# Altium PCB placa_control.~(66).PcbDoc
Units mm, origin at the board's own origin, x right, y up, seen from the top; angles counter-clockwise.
Board outline 71.3 x 86.83 mm, 2 copper layers (Top Layer, Bottom Layer); 36 components, 32 nets, 145 pads, 101 vias.
Unrouted connection lines stored in the file: 1.
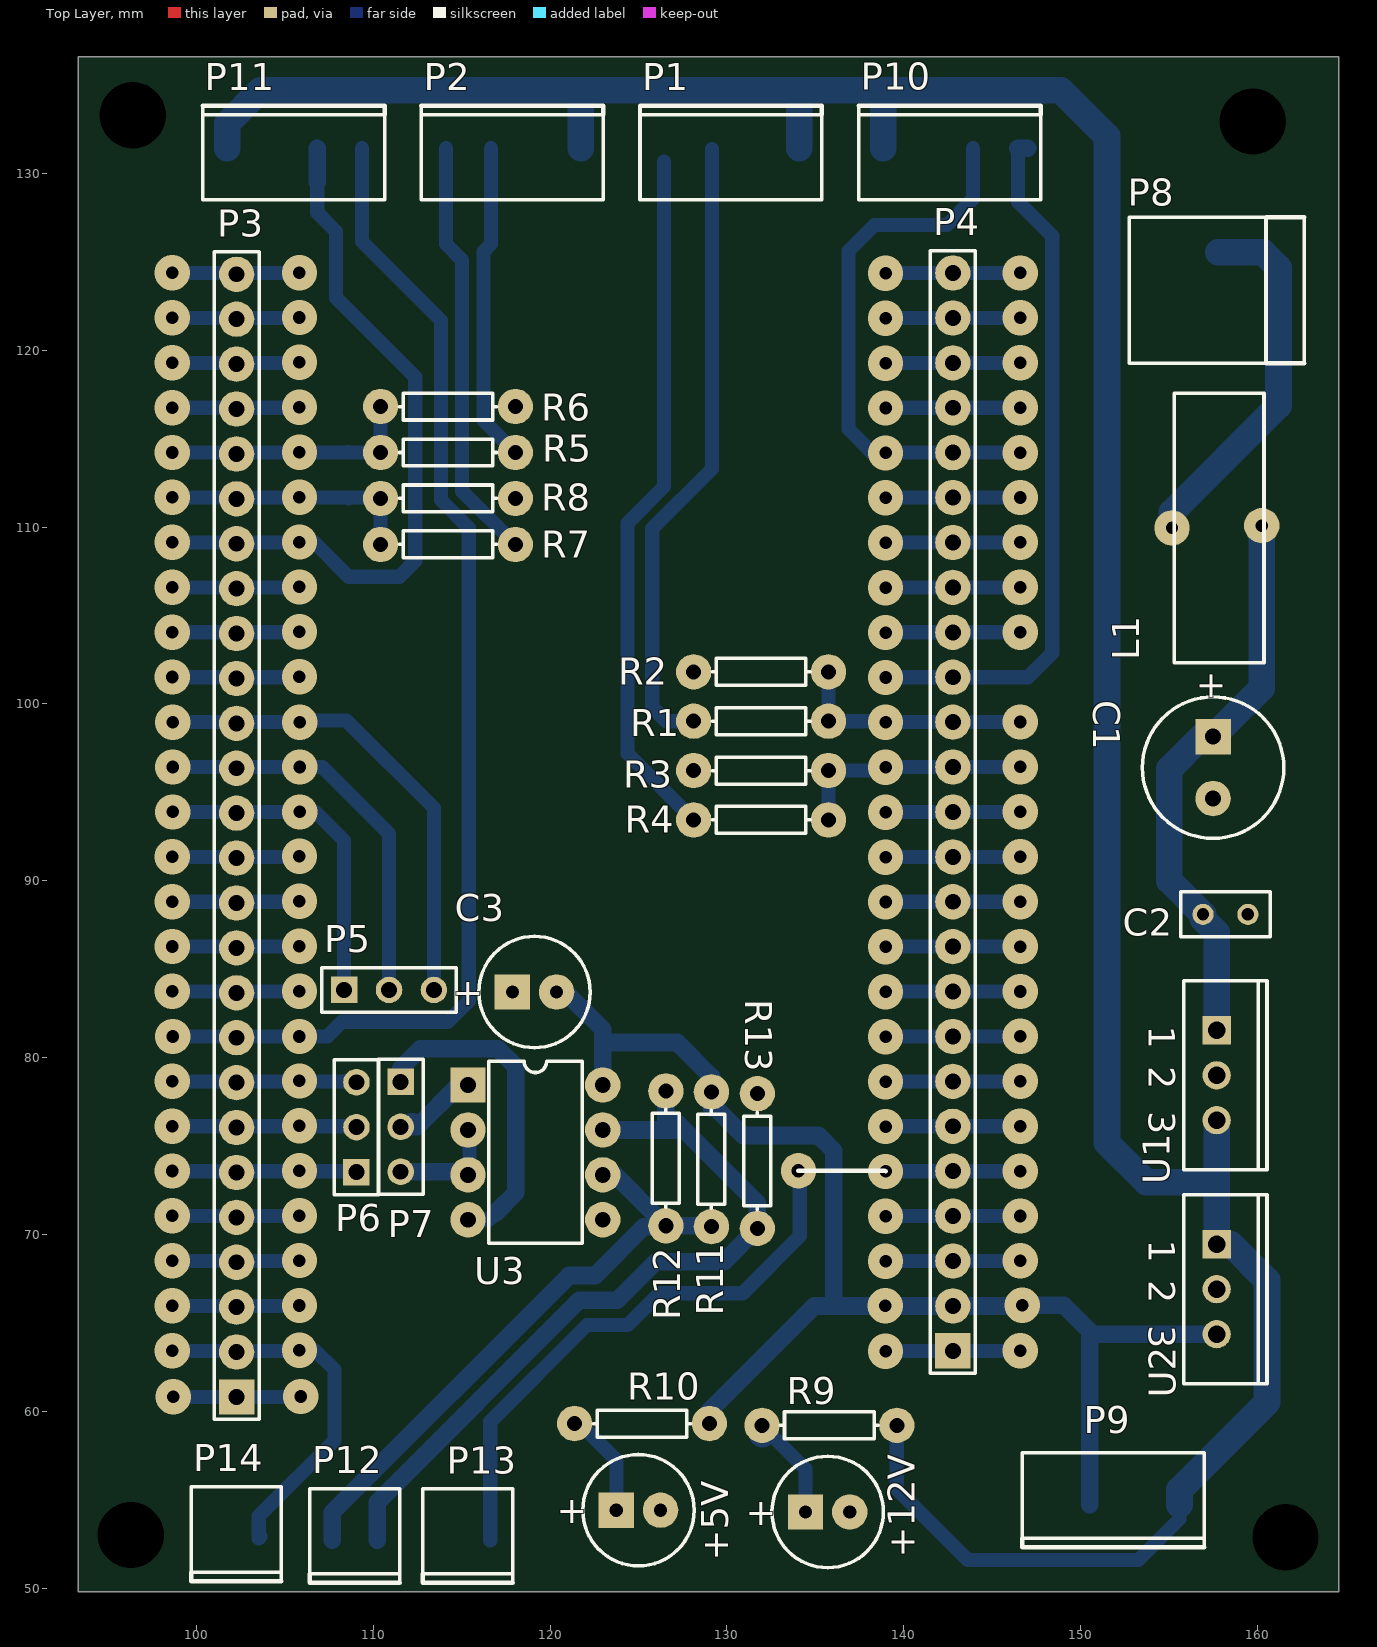
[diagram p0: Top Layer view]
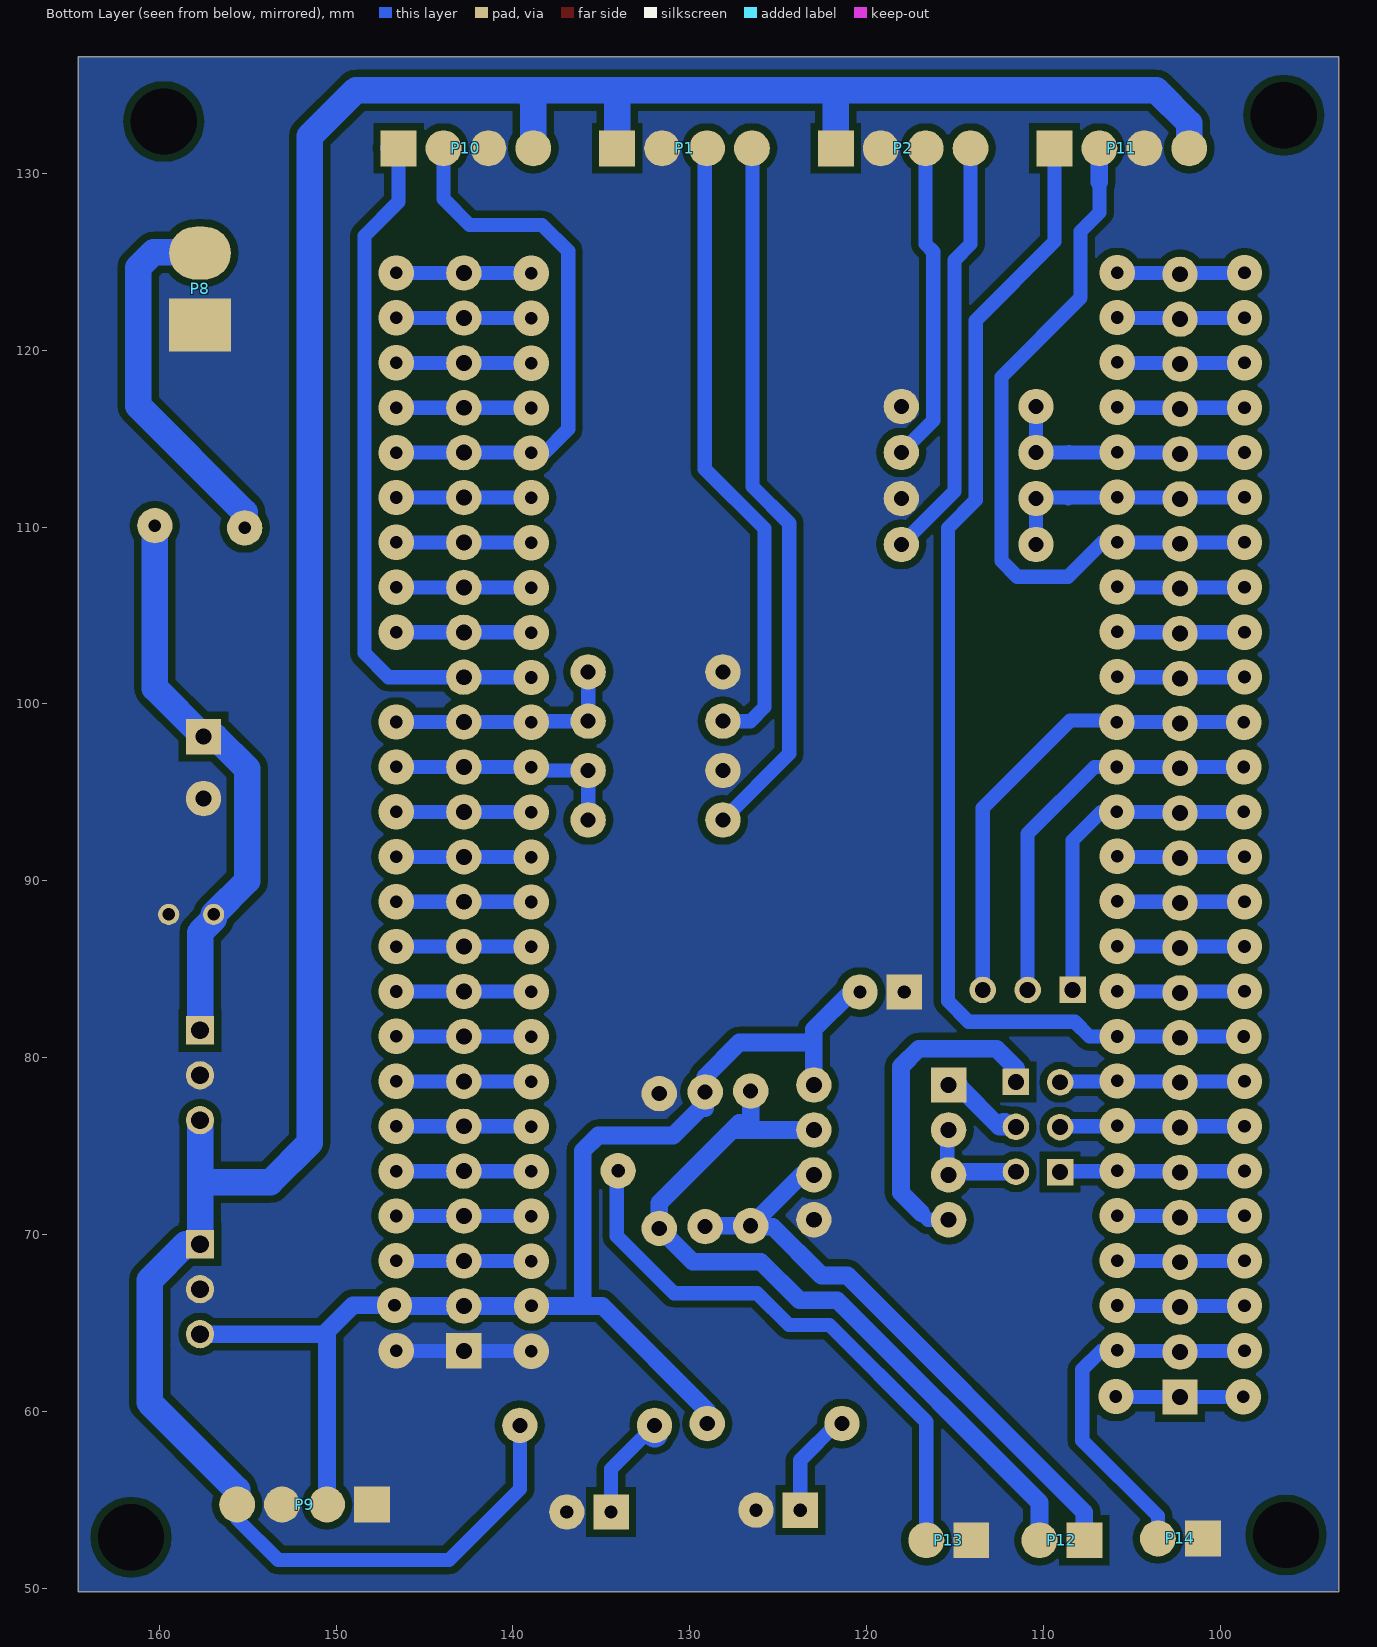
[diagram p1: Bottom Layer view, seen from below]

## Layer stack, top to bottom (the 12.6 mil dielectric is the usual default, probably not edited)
Top Layer: signal copper 0.0356
Dielectric: dielectric 0.32, FR-4, Dk 4.8
Bottom Layer: signal copper 0.0356

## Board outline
93.3,136.6 164.6,136.6 164.6,49.775 93.3,49.775

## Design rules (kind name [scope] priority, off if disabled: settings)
Clearance [All] p1: gap=0.4
ComponentClearance [All] p1: gap=0.254 collisioncheckmode=2 verticalgap=0.254
PlaneConnect [All] p1: planeconnectstyle=Direct reliefexpansion=0.508 reliefentries=4 reliefconductorwidth=0.6 reliefairgap=0.254
PolygonConnect [All] p1: connectstyle=Direct reliefconductorwidth=0.6 reliefentries=4 polygonreliefangle="90 Angle"
RoomDefinition REGULADOR [InComponentClass('REGULADOR')] p1: confinementstyle=ConfineIn formatcopy=TRUE lockcomponents=FALSE outline 119.85,49.75 164.625,49.75 164.625,133.175 119.85,133.175
RoomDefinition INTERFAZ [InComponentClass('INTERFAZ')] p2: confinementstyle=ConfineIn formatcopy=TRUE lockcomponents=FALSE outline 106.825,64.6 139.725,64.6 139.725,90 106.825,90
RoomDefinition ENCODER [InComponentClass('ENCODER')] p3: confinementstyle=ConfineIn formatcopy=TRUE lockcomponents=FALSE outline 149.05,93.65 149.05,135.875 98.875,135.875 98.875,93.65
RoomDefinition BOARD-ARM [InComponentClass('BOARD-ARM')] p4: confinementstyle=ConfineIn formatcopy=TRUE lockcomponents=FALSE outline 147.988,49.325 95.35,49.325 95.35,129.85 147.988,129.85
RoomDefinition placa_control_esquema [InComponentClass('placa_control_esquema')] p5: confinementstyle=ConfineIn formatcopy=TRUE lockcomponents=FALSE outline 93.3,49.75 164.6,49.75 164.6,136.6 93.3,136.6
RoutingVias [All] p1: holewidth=0.711 width=2 viastyle="Through Hole" minholewidth=0.711 minwidth=1.27 maxholewidth=0.711 maxwidth=2
SolderMaskExpansion [All] p1: expansion=0.102
TestPointUsage [All] p1: valid=0 allowmultiple=FALSE
Testpoint [All] p1: side=15 testpointundercomponent=TRUE minsize=1.016 maxsize=2.54 preferedsize=1.524 minholesize=0 maxholesize=1.016 preferedholesize=0.813 testpointgrid=0.025 style=1023 order=0123456789
Width [All] p1: maxlimit=1.5 minlimit=0.8 preferedwidth=0.8
17 further rules are at their usual default settings.

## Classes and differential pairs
component class placa_control_esquema: P9 P10 P11
component class REGULADOR: +5V +12V C1 C2 L1 P8 R9 R10 U1 U2
component class BOARD-ARM: P3 P4 P5 P6 P7 P13 P14
component class ENCODER: P1 P2 R1 R2 R3 R4 R5 R6 R7 R8
component class INTERFAZ: C3 P12 R11 R12 R13 U3

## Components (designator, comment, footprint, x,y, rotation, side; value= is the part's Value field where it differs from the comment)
+5V "LED2" CAPPR2.5-6.3X5 125,54.4 r0 top
+12V "LED2" CAPPR2.5-6.3X5 135.7,54.3 r0 top
C1 "Cap Pol3" CAPPR3.5-8X15 157.5,96.4 r270 top
C2 "Cap" RAD-0.1 158.2,88.1 r180 top
C3 "Cap" CAPPR2.5-6.3X5 119.119,83.708 r0 top
L1 "Inductor Iron" bobina_Choque 155.3,112.5 r270 top
P1 "Header 4" HDR1X5 126.483,139.05 r180 top
P2 "Header 4" HDR1X5 114.117,139.05 r180 top
P3 "header26" HDR1x26 107.35,93.825 r90 top
P4 "Header 25" HDR1X25 142.78,63.415 r90 top
P5 "Header 3" HDR1X3 108.35,83.825 r0 top
P6 "Header 3" HDR1X3 109.05,73.525 r90 top
P7 "Header 3" HDR1X3 111.55,78.625 r270 top
P8 "Header 2" pwheader1x2 157.7,123.6 r90 top
P9 "Header 4" HDR1X5 155.6,47.1 r0 top
P10 "Header 4" HDR1X5 138.85,139.05 r180 top
P11 "Header 4" HDR1X5 101.75,139.05 r180 top
P12 "Header 2" wf2s 115.3,52.7 r0 top
P13 "Header 2" wf2s 121.7,52.7 r0 top
P14 "Header 2" wf2s 108.6,52.8 r0 top
R1 "metal film 2%" AXIAL-0.3 131.934,99.027 r180 top
R2 "metal film 2%" AXIAL-0.3 131.934,101.819 r0 top
R3 "metal film 2%" AXIAL-0.3 131.934,93.443 r180 top
R4 "metal film 2%" AXIAL-0.3 131.934,96.235 r0 top
R5 "metal film 2%" AXIAL-0.3 114.225,114.225 r0 top
R6 "metal film 2%" AXIAL-0.3 114.225,116.825 r180 top
R7 "metal film 2%" AXIAL-0.3 114.225,109.025 r0 top
R8 "metal film 2%" AXIAL-0.3 114.225,111.625 r180 top
R9 "Carbon 1/8w 5%" AXIAL-0.3 135.8,59.2 r0 top
R10 "Carbon 1/8w 5%" AXIAL-0.3 125.2,59.3 r0 top
R11 "Carbon 1/8w 5%" AXIAL-0.3 129.125,74.25 r90 top
R12 "Carbon 1/8w 5%" AXIAL-0.3 126.551,74.3 r270 top
R13 "Carbon 1/8w 5%" AXIAL-0.3 131.725,74.15 r270 top
U1 "LM78L12ACZ" T03B 157.7,79 r270 top
U2 "LM78L05ACZ" T03B 157.7,66.9 r270 top
U3 "SN75176BP" 626-05 119.169,74.64 r270 top

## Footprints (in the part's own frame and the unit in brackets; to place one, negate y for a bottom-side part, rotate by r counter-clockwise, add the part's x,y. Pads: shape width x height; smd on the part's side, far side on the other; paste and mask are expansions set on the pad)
626-05 [mm] "DIP; 8 Leads; Row Spacing 7.62 mm; Pitch 2.54 mm"
  rect 2x2 hole 0.9: 1(-3.81,-3.81)
  round 2 hole 0.9: 2(-1.27,-3.81) 3(1.27,-3.81) 4(3.81,-3.81) 5(3.81,3.81) 6(1.27,3.81) 7(-1.27,3.81) 8(-3.81,3.81)
  silkscreen extent -5.15,-2.65 5.15,2.65
AXIAL-0.3 [mm] "Resistor; 2 Leads"
  round 2 hole 0.85: 1(-3.81,0) 2(3.81,0)
  silkscreen extent -2.77,-0.76 2.77,0.76
bobina_Choque [mm]
  round 2 hole 0.7: 1(2.54,-0.127) 2(2.413,4.953)
  silkscreen extent -5.08,0 10.16,5.08
CAPPR2.5-6.3X5 [mm] "Capacitor, Electrolytic, Radial; Body 6.3 x 5 mm (Dia.xH typ); Pin Spacing 2.5 mm (typ)"
  rect 2x2 hole 0.75: 1(-1.25,0)
  round 2 hole 0.75: 2(1.25,0)
  silkscreen extent -3.15,-3.15 3.15,3.15
CAPPR3.5-8X15 [mm] "Capacitor, Electrolytic, Radial; Body 8 x 15 mm (Dia.xH typ); Pin Spacing 3.5 mm (typ)"
  rect 2x2 hole 0.9: 1(-1.75,0)
  round 2 hole 0.9: 2(1.75,0)
  silkscreen extent -4,-4 4,4
HDR1X3 [mm] "Connector; Header; 3 Position"
  rect 1.5x1.5 hole 0.9: 1(0,0)
  round 1.5 hole 0.9: 2(2.54,0) 3(5.08,0)
  silkscreen extent -1.27,-1.27 6.35,1.27
HDR1X5 [mil]
  rect 80x80 smd far side: 1(-300,300)
  round 80 smd far side: 2(-200,300) 3(-100,300) 4(0,300)
  silkscreen extent -350,205 55,415
HDR1X25 [mm] "Connector; Header; 25 Position"
  rect 2x2 hole 0.9: 1(0,0)
  round 2 hole 0.9: 2(2.54,0) 3(5.08,0) 4(7.62,0) 5(10.16,0) 6(12.7,0) 7(15.24,0) 8(17.78,0) 9(20.32,0) 10(22.86,0) 11(25.4,0) 12(27.94,0) 13(30.48,0) 14(33.02,0) 15(35.56,0) 16(38.1,0) 17(40.64,0) 18(43.18,0) 19(45.72,0) 20(48.26,0) 21(50.8,0) 22(53.34,0) 23(55.88,0) 24(58.42,0) 25(60.96,0)
  silkscreen extent -1.27,-1.27 62.23,1.27
HDR1x26 [mm]
  rect 2x2 hole 0.9: 1(-33.02,5.08)
  round 2 hole 0.9: 2(-30.48,5.08) 3(-27.94,5.08) 4(-25.4,5.08) 5(-22.86,5.08) 6(-20.32,5.08) 7(-17.78,5.08) 8(-15.24,5.08) 9(-12.7,5.08) 10(-10.16,5.08) 11(-7.62,5.08) 12(-5.08,5.08) 13(-2.54,5.08) 14(0,5.08) 15(2.54,5.08) 16(5.08,5.08) 17(7.62,5.08) 18(10.16,5.08) 19(12.7,5.08) 20(15.24,5.08) 21(17.78,5.08) 22(20.32,5.08) 23(22.86,5.08) 24(25.4,5.08) 25(27.94,5.08) 26(30.48,5.08)
  silkscreen extent -34.29,3.81 31.75,6.35
pwheader1x2 [mm]
  rect 3x3.5 smd far side: 1(-2.159,0)
  oval 3x3.5 smd far side: 2(1.905,0)
  silkscreen extent -4.32,-4.95 3.94,4.95
RAD-0.1 [mm] "Indicating Instrument; 2 Leads"
  round 1.2 hole 0.7: 1(-1.27,0) 2(1.27,0)
  silkscreen extent -2.54,-1.27 2.54,1.27
T03B [mm] "TO, Thru-Hole, Vertical, Heatsink Mounted; 3 In-Line Leads; Pitch 2.54 mm"
  rect 1.6x1.6 hole 1: 1(-2.54,0)
  round 1.6 hole 1: 2(0,0) 3(2.54,0)
  silkscreen extent -5.35,-1.85 5.35,2.85
wf2s [mil]
  rect 80x80 smd far side: 1(-300,0)
  round 80 smd far side: 2(-200,0)
  silkscreen extent -350,-95 -150,115

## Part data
+5V +12V: "Typical RED, GREEN, YELLOW, AMBER GaAs LED"
C1: "Polarized Capacitor 35V"
C2 C3: "Capacitor"
L1: "Magnetic-Core Inductor"
P1 P2 P9 P10 P11: "Header, 4-Pin"
P3: library part Component_1
P4: "Header, 25-Pin"
P5 P6 P7: "Header, 3-Pin"
P8 P12 P13 P14: "Header, 2-Pin"
R1 R2 R3 R4 R5 R6 R7 R8 R9 R10 R11 R12 R13: library part "Res Semi", "Semiconductor Resistor"
U1 U2: "3-Terminal Positive Regulator"
U3: "Differential Bus Transceiver"

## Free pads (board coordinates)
  round 1.524 hole 3.75: 0(96.275,53) 0(96.4,133.3) 0(159.75,132.95) 0(161.6,52.875)
  round 2 hole 0.762: 0(134.05,73.6)

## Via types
v1: diameter 2, hole 0.711, Top Layer to Bottom Layer, 101 vias

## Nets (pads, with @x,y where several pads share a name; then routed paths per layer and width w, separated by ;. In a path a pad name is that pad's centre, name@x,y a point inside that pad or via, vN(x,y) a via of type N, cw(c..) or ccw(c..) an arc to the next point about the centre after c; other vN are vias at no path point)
+5V: C3.2 P4.2 P9.2 R10.2 R11.2 U2.3 U3.8 | length 71.6
  Bottom Layer w1: C3.2@120.867,83.708 122.979,81.596 U3.8 U3.8@123.2,78.45 ; 122.979,80.85 127.2,80.85 R11.2@129.125,78.925 ; R10.2 129.01,60.01 134.955,65.955 P4.2 142.785,65.95 v1@146.05,65.95 ; R11.2@129.125,77.15 129.125,77.4 130.932,75.593 135.182,75.593 136.05,74.725 136.05,66.05 ; v1(146.7,66) 149.05,66 150.69,64.36 U2.3 ; P9.2 150.52,64.18
  other v1: 138.95,65.955
+12V: P1.1 P2.1 P9.4 P10.4 P11.4 R9.2 U1.3 U2.1 | length 173.9
  Bottom Layer w0.8: R9.2 139.61,55.59 143.625,51.575 153.275,51.575 155.6,53.9 P9.4
  Bottom Layer w1.5: P11.4 101.75,132.85 103.625,134.725 148.875,134.725 151.5,132.1 151.5,75.175 153.725,72.95 157.7,72.95 ; P2.1 121.737,134.212 121.75,134.225 ; P1.1 134.103,134.178 134.15,134.225 ; P10.4 138.85,134.15 138.925,134.225 ; P9.4 155.6,55.55 160.55,60.5 160.55,63.725 ; U1.3 U2.1 158.51,69.44 160.55,67.4 160.55,63.85
D/~E: P7.3 U3.2 U3.3 | length 6.7
  Bottom Layer w0.8: U3.3 115.435,73.445 115.435,75.94 U3.2@115.475,75.9
  Bottom Layer w1: P7.3 115.184,73.545 U3.3 ; U3.3@115.34,73.845 U3.3@115.435,73.75
D/~E_0: P3.14 P5.1 | length 18.8
  Bottom Layer w0.8: v1(98.665,93.895) 106.73,93.895 108.35,92.275 P5.1
  other v1: 105.85,93.895
D/~E_1: P3.6 P6.1 | length 10.4
  Bottom Layer w0.8: v1@98.665,73.575 109,73.575 P6.1
  other v1: 98.625,73.585 105.825,73.6
DRIVER: P7.1 U3.4 | length 18.6
  Bottom Layer w0.8: U3.4 116.53,70.83 116.912,71.212
  Bottom Layer w1: P7.1 111.55,79.4 112.65,80.5 117.05,80.5 118.05,79.5 118.05,72.35 116.912,71.212
GND: +5V.2 +12V.2 C1.2 C2.1 C3.1 P1.2 P2.2 P4.1 P8.1 P9.1 P9.3 P10.3 P11.3 P13.1 P14.1 R2.1 R4.1 R6.1 R8.1 R13.1 U1.2 U2.2 U3.5 | length 7.2
  Bottom Layer w0.8: v1@139.28,63.415 v1@146.465,63.415
  other v1: 138.975,63.4 146.6,63.42
IN_B_L: P3.2 P14.2 | length 21.1
  Bottom Layer w0.8: v1@98.665,63.415 v1@105.85,63.415 ; P14.2@103.625,52.905 P14.2 103.52,54.07 107.8,58.35 107.8,62.35 106.71,63.44 v1(105.825,63.44)
  other v1: 98.625,63.425
IN_SD_1: P4.21 P10.2 | length 31
  Bottom Layer w0.8: v1(138.975,114.2) 138.225,114.2 136.875,115.55 136.875,125.625 138.35,127.1 142.45,127.1 143.93,128.58 P10.2 ; v1@139.28,114.215 v1@146.465,114.215
  other v1: 146.6,114.22
IN_SD_2: P3.20 P11.2 | length 42.5
  Bottom Layer w0.8: v1@98.665,109.135 v1@105.85,109.135 ; v1(105.825,109.16) 106.64,109.16 108.6,107.2 111.475,107.2 112.375,108.1 112.375,118.5 107.9,122.975 107.9,126.725 106.83,127.795 P11.2
  Bottom Layer w1: 106.83,129.505 P11.2
  other v1: 98.625,109.145
Net+5V_1: +5V.1 R10.1 | length 6
  Bottom Layer w0.8: R10.1 121.675,59.3 123.75,57.225 +5V.1
Net+12V_1: +12V.1 R9.1 | length 6.4
  Bottom Layer w0.8: R9.1 134.45,56.74 +12V.1
  Bottom Layer w1.5: R9.1@131.99,58.71 R9.1
NetC1_1: C1.1 C2.2 L1.2 U1.1 | length 32.2
  Bottom Layer w1.5: U1.1 157.7,87.075 156.93,87.845 C2.2 155.03,90 155.025,90 155.025,96.325 156.85,98.15 C1.1 160.253,100.903 L1.2
NetL1_1: L1.1 P8.2 | length 21
  Bottom Layer w1.5: L1.1 155.173,110.848 161.2,116.875 161.2,124.675 160.325,125.55 P8.2@157.8,125.55
NetP1_3: P1.3 R1.2 | length 35.7
  Bottom Layer w0.8: R1.2 126.573,99.027 125.775,99.825 125.775,109.925 129.15,113.3 P1.3@129.15,131.4
NetP1_4: P1.4 R3.2 | length 39.6
  Bottom Layer w0.8: P1.4@126.45,130.675 126.45,112.297 124.375,110.222 124.375,97.192 R3.2
NetP2_3: P2.3 R5.2 | length 18.1
  Bottom Layer w0.8: P2.3 116.657,126.009 116.225,125.577 116.225,116.035 R5.2
NetP2_4: P2.4 R7.2 | length 24
  Bottom Layer w0.8: P2.4 114.117,126.008 115.025,125.1 115.025,112.035 R7.2
NetP3_21: P3.21 R7.1 R8.2 | length 14.5
  Bottom Layer w0.8: v1@98.525,111.675 R8.2@110.365,111.675 ; 108.54,111.675 108.59,111.625 ; R7.1 R8.2
  other v1: 98.625,111.685 105.825,111.7
NetP3_22: P3.22 R5.1 R6.2 | length 14.4
  Bottom Layer w0.8: v1@98.625,114.215 R5.1@110.405,114.215 ; 108.55,114.245 108.58,114.215 ; R5.1 R6.2
  other v1: 98.625,114.225 105.825,114.24
NetP4_14: P4.14 R3.1 R4.2 | length 13
  Bottom Layer w0.8: R3.1 R4.2 v1@138.79,96.235 ; v1@139.28,96.435 v1@146.465,96.435
  other v1: 138.975,96.42 146.6,96.44
NetP4_15: P4.15 R1.1 R2.2 | length 13.1
  Bottom Layer w0.8: R2.2 R1.1 v1@138.908,99.027 ; v1@139.28,98.975 v1@146.465,98.975
  other v1: 138.975,98.96 146.6,98.98
NetP12_1: P12.1 R11.1 R12.2 U3.6 | length 33.9
  Bottom Layer w1: P12.1 107.68,54.28 121.075,67.675 122.55,67.675 125.3,70.425 125.9,70.425 125.965,70.49 129.075,70.49 R11.1 ; U3.6@123.671,73.37 R12.2@126.291,70.75 ; R12.2 R12.2@126.551,70.876
NetP12_2: P12.2 R12.1 R13.2 U3.7 | length 45
  Bottom Layer w1: P12.2 110.22,54.84 121.655,66.275 123.795,66.275 125.98,68.46 129.835,68.46 131.725,70.35 131.725,71.775 127.201,76.299 126.551,76.299 R12.1 R12.1@126.591,78.15 ; U3.7 127.59,75.91
PWM_1: P4.16 P10.1 | length 39.6
  Bottom Layer w0.8: v1@139.28,101.515 147.04,101.515 148.4,102.875 148.4,126.475 146.47,128.405 P10.1
  Bottom Layer w1: P10.1 P10.1@147.02,131.43
  other v1: 138.975,101.5
PWM_2: P3.9 P11.1 | length 68.3
  Bottom Layer w0.8: v1(98.665,81.195) 107.395,81.195 108.225,82.025 114.225,82.025 115.4,83.2 115.4,109.963 113.825,111.538 113.825,121.7 109.37,126.155 P11.1
  other v1: 105.825,81.195
RECIEVER: P7.2 U3.1 | length 5.1
  Bottom Layer w1: P7.2 112.485,76.085 U3.1@114.875,78.475 ; P7.2@112.15,76.375 112.25,76.375 ; U3.1@114.775,78.475 U3.1@115.5,78.475
RESET: P4.5 P13.2 pad.0@134.05,73.6 | length 39.4
  Bottom Layer w0.8: P13.2 116.62,59.402 122.089,64.87 124.395,64.87 126.2,66.675 130.9,66.675 134.125,69.9 pad.0@134.125,73.575 ; v1@139.28,73.575 v1@146.465,73.575
  other v1: 138.975,73.56 146.6,73.58
RX_0: P3.15 P5.2 | length 22.6
  Bottom Layer w0.8: v1(98.665,96.435) 107.115,96.435 110.89,92.66 P5.2
  other v1: 105.85,96.435
RX_1: P3.7 P6.2 | length 10.4
  Bottom Layer w0.8: v1@98.665,76.115 109,76.115 P6.2
  other v1: 98.625,76.125 105.825,76.14
TX_0: P3.16 P5.3 | length 27.1
  Bottom Layer w0.8: v1(98.665,98.975) v1(105.85,98.975) ; v1@105.875,99.075 108.475,99.075 113.43,94.12 P5.3
TX_1: P3.8 P6.3 | length 10.4
  Bottom Layer w0.8: v1@98.665,78.655 109,78.655 P6.3
  other v1: 98.625,78.665 105.825,78.68
pads on no net: P3.1 P3.3 P3.4 P3.5 P3.10 P3.11 P3.12 P3.13 P3.17 P3.18 P3.19 P3.23 P3.24 P3.25 P3.26 P4.3 P4.4 P4.6 P4.7 P4.8 P4.9 P4.10 P4.11 P4.12 P4.13 P4.17 P4.18 P4.19 P4.20 P4.22 P4.23 P4.24 P4.25
copper on no net: | length 237.1
  Bottom Layer w0.8: v1@98.665,65.955 v1@105.85,65.955 ; v1@98.665,68.495 v1@105.85,68.495 ; v1@98.665,71.035 v1@105.85,71.035 ; v1@98.665,83.735 v1@105.825,83.735 ; v1@98.665,86.275 v1@105.85,86.275 ; v1@98.665,88.815 v1@105.85,88.815 ; v1@98.665,91.355 v1@105.85,91.355 ; v1@98.665,101.515 v1@105.85,101.515 ; v1@98.665,104.055 v1@105.85,104.055 ; v1@98.665,106.595 v1@105.85,106.595 ; v1@98.665,116.755 v1@105.85,116.755 ; v1@98.665,119.295 v1@105.85,119.295 ; v1@98.665,121.835 v1@105.85,121.835 ; v1@98.665,124.375 v1@105.85,124.375 ; v1@98.735,60.805 v1@105.92,60.805 ; v1@139.28,68.495 v1@146.465,68.495 ; v1@139.28,71.035 v1@146.465,71.035 ; v1@139.28,76.115 v1@146.465,76.115 ; v1@139.28,78.655 v1@146.465,78.655 ; v1@139.28,81.195 v1@146.465,81.195 ; v1@139.28,83.735 v1@146.465,83.735 ; v1@139.28,86.275 v1@146.465,86.275 ; v1@139.28,88.815 v1@146.465,88.815 ; v1@139.28,91.355 v1@146.465,91.355 ; v1@139.28,93.895 v1@146.465,93.895 ; v1@139.28,104.055 v1@146.465,104.055 ; v1@139.28,106.595 v1@146.465,106.595 ; v1@139.28,109.135 v1@146.465,109.135 ; v1@139.28,111.675 v1@146.465,111.675 ; v1@139.28,116.755 v1@146.465,116.755 ; v1@139.28,119.295 v1@146.465,119.295 ; v1@139.28,121.835 v1@146.465,121.835 ; v1@139.28,124.375 v1@146.465,124.375
  other v1: 98.695,60.815 105.895,60.83 98.625,65.965 105.825,65.98 138.975,68.48 98.625,68.505 146.6,68.5 105.825,68.52 138.975,71.02 98.625,71.045 146.6,71.04 105.825,71.06 138.975,76.1 146.6,76.12 138.975,78.64 146.6,78.66 138.975,81.18 146.6,81.2 138.975,83.72 98.625,83.745 146.6,83.74 105.825,83.76 138.975,86.26 98.625,86.285 146.6,86.28 105.825,86.3 138.975,88.8 98.625,88.825 146.6,88.82 105.825,88.84 138.975,91.34 98.625,91.365 146.6,91.36 105.825,91.38 138.975,93.88 146.6,93.9 98.625,101.525 105.825,101.54 138.975,104.04 98.625,104.065 146.6,104.06 105.825,104.08 138.975,106.58 98.625,106.605 146.6,106.6 105.825,106.62 138.975,109.12 146.6,109.14 138.975,111.66 146.6,111.68 138.975,116.74 98.625,116.765 146.6,116.76 105.825,116.78 138.975,119.28 98.625,119.305 146.6,119.3 105.825,119.32 138.975,121.82 98.625,121.845 146.6,121.84 105.825,121.86 138.975,124.36 98.625,124.385 146.6,124.38 105.825,124.4

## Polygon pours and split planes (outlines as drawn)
GND on Bottom Layer "plano_señal_fuerte" (solid, remove dead copper, pour order 1000): 93.325,136.614 93.387,136.65 164.625,136.65 164.594,136.632 164.594,49.868 164.625,49.85 93.481,49.85 93.387,49.905 93.325,49.941

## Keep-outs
Drill Guide:
  rectangle: 100.025,56.1 145.425,126.3

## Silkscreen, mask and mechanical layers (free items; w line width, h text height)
Top Overlay:
  lines w0.254: 134.05,73.6 138.935,73.6 138.975,73.56

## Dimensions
164.7,142.5 to 93.325,142.575 on Top Layer
169.675,136.65 to 167.925,50.15 on Bottom Layer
